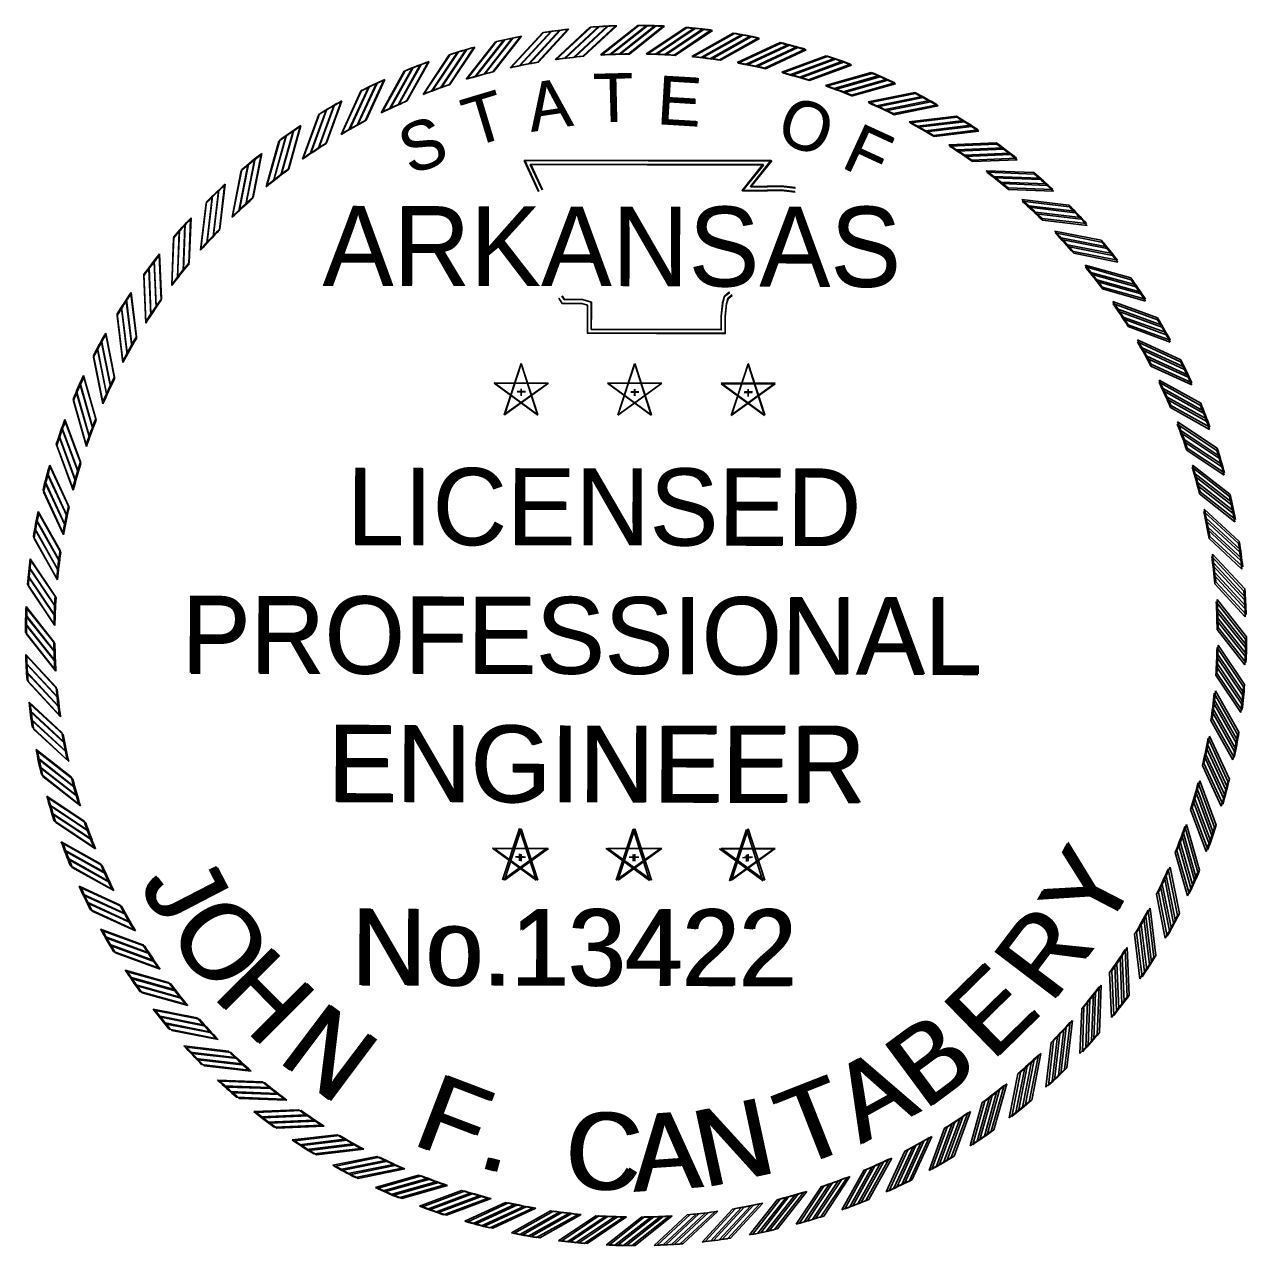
# Model space of a CAD drawing. Extents: x 1373862 to 1376999, y 1168398 to 1170455.
# Drawn here: x 1376755.4 to 1376998.5, y 1168428.9 to 1168671.8 of the extents above; entities that cross this region are included whole.
import ezdxf

# ---------------------------------------------------------------- set-up
doc = ezdxf.new("R2010")
doc.units = 0
doc.layers.add('Default', color=7, linetype='Continuous')

# ---------------------------------------------------------------- blocks, each defined once
blk = doc.blocks.new('STAR')
at = {"layer": 'Default'}
for p, q in [((-0.0001, 0.0615), (-0.0366, -0.0504)), ((0.0362, -0.0503), (0, 0.0617)), ((0.0587, 0.0188), (-0.059, 0.0189)), ((-0.0589, 0.0188), (0.0363, -0.0505)), ((-0.0365, -0.0503), (0.0589, 0.0188)), ((-0.0085, 0), (0.009, 0)), ((0, 0.0063), (0, -0.0085))]:
    blk.add_line(p, q, dxfattribs=at)
blk = doc.blocks.new('RP')
at = {"layer": 'Default'}
for p, q in [((-0.0781, 1.2656), (0.003, 1.33)), ((-0.058, 1.2667), (0.0216, 1.3299)), ((-0.0375, 1.2674), (0.0405, 1.3294)), ((-0.0176, 1.2679), (0.059, 1.3287))]:
    blk.add_line(p, q, dxfattribs=at)
for radius, start, end in [(1.33, 87.4562, 89.8699), (1.268, 90.7933, 93.5307)]:
    blk.add_arc((0, 0), radius, start, end, dxfattribs=at)

msp = doc.modelspace()

# ---------------------------------------------------------------- linework, layer by layer
at = {"layer": 'Default'}
for points in [[(1376857.59, 1168638.63), (1376854.76, 1168644.77), (1376903.8, 1168644.8), (1376899.7, 1168639.65), (1376903.03, 1168639.69), (1376905.82, 1168639.73), (1376908.6, 1168639.43)], [(1376857.69, 1168638.66), (1376854.88, 1168644.81), (1376903.92, 1168644.67), (1376899.8, 1168639.54), (1376903.13, 1168639.57), (1376905.92, 1168639.6), (1376908.7, 1168639.28)], [(1376858.3, 1168638.96), (1376855.97, 1168643.99), (1376902.19, 1168644.02), (1376898.07, 1168638.85), (1376903.04, 1168638.92), (1376905.78, 1168638.95), (1376908.51, 1168638.65)], [(1376858.39, 1168638.99), (1376856.09, 1168644.03), (1376902.3, 1168643.9), (1376898.17, 1168638.75), (1376903.14, 1168638.79), (1376905.88, 1168638.82), (1376908.61, 1168638.51)], [(1376896.07, 1168618.08), (1376895.23, 1168617.4), (1376894.96, 1168616.38), (1376894.68, 1168613.84), (1376894.68, 1168610.45), (1376867.3, 1168610.45), (1376867.3, 1168615.03), (1376867.3, 1168616.04), (1376866.19, 1168616.38), (1376862.3, 1168616.38), (1376861.61, 1168617.44)], [(1376896.1, 1168617.98), (1376895.26, 1168617.3), (1376894.98, 1168616.29), (1376894.69, 1168613.75), (1376894.68, 1168610.36), (1376867.3, 1168610.45), (1376867.32, 1168615.03), (1376867.32, 1168616.04), (1376866.21, 1168616.38), (1376862.32, 1168616.4), (1376861.63, 1168617.46)], [(1376895.58, 1168618.68), (1376894.55, 1168617.84), (1376894.19, 1168616.53), (1376893.9, 1168613.88), (1376893.9, 1168611.23), (1376868.08, 1168611.23), (1376868.08, 1168615.03), (1376868.08, 1168616.62), (1376866.31, 1168617.16), (1376862.72, 1168617.16), (1376862.26, 1168617.86)], [(1376895.61, 1168618.58), (1376894.58, 1168617.75), (1376894.21, 1168616.43), (1376893.91, 1168613.79), (1376893.91, 1168611.13), (1376868.08, 1168611.22), (1376868.1, 1168615.02), (1376868.1, 1168616.61), (1376866.33, 1168617.16), (1376862.74, 1168617.17), (1376862.28, 1168617.88)]]:
    msp.add_lwpolyline(points, dxfattribs=at)

# ---------------------------------------------------------------- block references
for name, p, xscale, yscale, rotation in [('RP', (1376877.07, 1168550.39), 91.17655343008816, 91.1765534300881, 4.500000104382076), ('RP', (1376876.87, 1168550.35), 91.17655343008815, 91.17655343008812, 4.304199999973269), ('RP', (1376877.07, 1168550.39), 91.17655343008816, 91.1765534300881, 1.0438208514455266e-07), ('RP', (1376876.87, 1168550.35), 91.17655343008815, 91.1765534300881, -0.19580000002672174), ('RP', (1376877.07, 1168550.39), 91.17655343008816, 91.17655343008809, -4.499999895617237), ('RP', (1376876.87, 1168550.35), 91.17655343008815, 91.17655343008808, -4.695800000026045), ('RP', (1376877.07, 1168550.39), 91.17655343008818, 91.17655343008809, -8.999999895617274), ('RP', (1376876.87, 1168550.35), 91.17655343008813, 91.17655343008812, -9.19580000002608), ('RP', (1376877.07, 1168550.39), 91.17655343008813, 91.17655343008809, 13.500000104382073), ('RP', (1376876.87, 1168550.35), 91.17655343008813, 91.17655343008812, 13.304199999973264), ('RP', (1376877.07, 1168550.39), 91.17655343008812, 91.17655343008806, 9.000000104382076), ('RP', (1376876.87, 1168550.35), 91.17655343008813, 91.17655343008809, 8.804199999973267), ('RP', (1376877.07, 1168550.39), 91.17655343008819, 91.17655343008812, -13.499999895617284), ('RP', (1376876.87, 1168550.35), 91.17655343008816, 91.17655343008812, -13.695800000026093), ('RP', (1376877.07, 1168550.39), 91.17655343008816, 91.1765534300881, 18.00000010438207), ('RP', (1376876.87, 1168550.35), 91.17655343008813, 91.17655343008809, 17.80419999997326), ('RP', (1376877.07, 1168550.39), 91.17655343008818, 91.1765534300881, -17.99999989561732), ('RP', (1376876.87, 1168550.35), 91.17655343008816, 91.1765534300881, -18.195800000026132), ('RP', (1376877.07, 1168550.39), 91.17655343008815, 91.1765534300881, 22.50000010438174), ('RP', (1376876.87, 1168550.35), 91.17655343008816, 91.17655343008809, 22.304199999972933), ('RP', (1376877.07, 1168550.39), 91.17655343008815, 91.17655343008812, -22.499999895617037), ('RP', (1376876.87, 1168550.35), 91.17655343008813, 91.17655343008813, -22.695800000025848), ('RP', (1376877.07, 1168550.39), 91.17655343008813, 91.17655343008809, -26.999999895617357), ('RP', (1376876.87, 1168550.35), 91.17655343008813, 91.17655343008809, -27.19580000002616), ('RP', (1376877.07, 1168550.39), 91.17655343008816, 91.17655343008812, 27.00000010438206), ('RP', (1376876.87, 1168550.35), 91.17655343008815, 91.17655343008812, 26.80419999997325), ('RP', (1376876.87, 1168550.35), 91.17655343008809, 91.17655343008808, 31.30419999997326), ('RP', (1376877.07, 1168550.39), 91.17655343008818, 91.17655343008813, -31.49999989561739), ('RP', (1376876.87, 1168550.35), 91.17655343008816, 91.17655343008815, -31.695800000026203), ('RP', (1376877.07, 1168550.39), 91.1765534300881, 91.17655343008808, 31.500000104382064), ('RP', (1376876.87, 1168550.35), 91.1765534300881, 91.1765534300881, 35.804199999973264), ('RP', (1376877.07, 1168550.39), 91.17655343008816, 91.17655343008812, -35.99999989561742), ('RP', (1376876.87, 1168550.35), 91.17655343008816, 91.17655343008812, -36.195800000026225), ('RP', (1376877.07, 1168550.39), 91.17655343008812, 91.1765534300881, 36.00000010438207), ('RP', (1376877.07, 1168550.39), 91.17655343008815, 91.17655343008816, -40.499999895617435), ('RP', (1376876.87, 1168550.35), 91.17655343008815, 91.17655343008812, -40.69580000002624), ('RP', (1376877.07, 1168550.39), 91.17655343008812, 91.1765534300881, 40.50000010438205), ('RP', (1376876.87, 1168550.35), 91.17655343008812, 91.1765534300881, 40.30419999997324), ('RP', (1376877.07, 1168550.39), 91.17655343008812, 91.17655343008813, 45.00000010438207), ('RP', (1376876.87, 1168550.35), 91.17655343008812, 91.1765534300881, 44.80419999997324), ('RP', (1376877.07, 1168550.39), 91.17655343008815, 91.1765534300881, -44.99999989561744), ('RP', (1376876.87, 1168550.35), 91.17655343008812, 91.1765534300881, -45.19580000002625), ('RP', (1376877.07, 1168550.39), 91.17655343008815, 91.17655343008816, 49.500000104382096), ('RP', (1376876.87, 1168550.35), 91.17655343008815, 91.17655343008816, 49.30419999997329), ('RP', (1376877.07, 1168550.39), 91.1765534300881, 91.1765534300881, -49.499999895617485), ('RP', (1376876.87, 1168550.35), 91.1765534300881, 91.17655343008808, -49.695800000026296), ('RP', (1376877.07, 1168550.39), 91.17655343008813, 91.17655343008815, 54.00000010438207), ('RP', (1376876.87, 1168550.35), 91.17655343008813, 91.17655343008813, 53.804199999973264), ('RP', (1376877.07, 1168550.39), 91.17655343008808, 91.17655343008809, -53.999999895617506), ('RP', (1376876.87, 1168550.35), 91.17655343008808, 91.17655343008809, -54.1958000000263), ('RP', (1376876.87, 1168550.35), 91.1765534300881, 91.17655343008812, 58.304199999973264), ('RP', (1376877.07, 1168550.39), 91.1765534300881, 91.17655343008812, 58.50000010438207), ('RP', (1376877.07, 1168550.39), 91.1765534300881, 91.17655343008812, -58.49999989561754), ('RP', (1376876.87, 1168550.35), 91.17655343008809, 91.17655343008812, -58.69580000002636), ('RP', (1376876.87, 1168550.35), 91.17655343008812, 91.17655343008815, 62.804199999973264), ('RP', (1376877.07, 1168550.39), 91.17655343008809, 91.17655343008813, -62.999999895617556), ('RP', (1376876.87, 1168550.35), 91.17655343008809, 91.17655343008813, -63.19580000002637), ('RP', (1376877.07, 1168550.39), 91.17655343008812, 91.17655343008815, 63.000000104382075), ('STAR', (1376854.14, 1168598.85), 91.17655343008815, 91.1765534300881, -0.19580000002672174), ('STAR', (1376854.18, 1168598.8), 91.17655343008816, 91.1765534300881, 1.0438208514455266e-07), ('STAR', (1376876.69, 1168598.77), 91.17655343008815, 91.1765534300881, -0.19580000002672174), ('STAR', (1376876.73, 1168598.8), 91.17655343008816, 91.1765534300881, 1.0438208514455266e-07), ('STAR', (1376899.25, 1168598.69), 91.17655343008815, 91.1765534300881, -0.19580000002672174), ('STAR', (1376899.29, 1168598.8), 91.17655343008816, 91.1765534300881, 1.0438208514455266e-07), ('RP', (1376877.07, 1168550.39), 91.1765534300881, 91.17655343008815, -67.49999989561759), ('RP', (1376876.87, 1168550.35), 91.1765534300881, 91.17655343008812, 67.30419999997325), ('RP', (1376877.07, 1168550.39), 91.1765534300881, 91.17655343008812, 67.50000010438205), ('RP', (1376876.87, 1168550.35), 91.1765534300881, 91.17655343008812, -67.69580000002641), ('RP', (1376876.87, 1168550.35), 91.1765534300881, 91.17655343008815, -72.19580000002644), ('RP', (1376877.07, 1168550.39), 91.1765534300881, 91.17655343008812, -71.99999989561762), ('RP', (1376876.87, 1168550.35), 91.17655343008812, 91.17655343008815, 71.80419999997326), ('RP', (1376877.07, 1168550.39), 91.1765534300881, 91.17655343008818, 72.00000010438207), ('RP', (1376876.87, 1168550.35), 91.17655343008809, 91.17655343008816, 76.30419999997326), ('RP', (1376877.07, 1168550.39), 91.17655343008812, 91.17655343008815, 76.50000010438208), ('RP', (1376876.87, 1168550.35), 91.17655343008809, 91.17655343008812, -76.69580000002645), ('RP', (1376877.07, 1168550.39), 91.17655343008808, 91.1765534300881, -76.49999989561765), ('RP', (1376877.07, 1168550.39), 91.17655343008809, 91.17655343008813, -80.99999989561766), ('RP', (1376876.87, 1168550.35), 91.17655343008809, 91.17655343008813, 80.80419999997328), ('RP', (1376877.07, 1168550.39), 91.1765534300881, 91.17655343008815, 81.0000001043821), ('RP', (1376876.87, 1168550.35), 91.1765534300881, 91.17655343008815, -81.19580000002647), ('RP', (1376877.07, 1168550.39), 91.17655343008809, 91.17655343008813, -85.49999989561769), ('RP', (1376876.87, 1168550.35), 91.17655343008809, 91.17655343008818, 85.30419999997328), ('RP', (1376877.07, 1168550.39), 91.17655343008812, 91.17655343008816, 85.50000010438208), ('RP', (1376876.87, 1168550.35), 91.17655343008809, 91.17655343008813, -85.69580000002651), ('RP', (1376876.87, 1168550.35), 91.17655343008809, 91.17655343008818, -90.19580000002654), ('RP', (1376877.07, 1168550.39), 91.1765534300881, 91.17655343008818, -89.99999989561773), ('RP', (1376876.87, 1168550.35), 91.1765534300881, 91.17655343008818, 89.80419999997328), ('RP', (1376877.07, 1168550.39), 91.17655343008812, 91.17655343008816, 90.0000001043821), ('RP', (1376876.87, 1168550.35), 91.17655343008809, 91.17655343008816, -94.69580000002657), ('RP', (1376877.07, 1168550.39), 91.17655343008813, 91.17655343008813, -94.49999989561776), ('RP', (1376876.87, 1168550.35), 91.17655343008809, 91.17655343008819, 94.30419999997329), ('RP', (1376877.07, 1168550.39), 91.1765534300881, 91.1765534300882, 94.5000001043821), ('RP', (1376876.87, 1168550.35), 91.1765534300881, 91.17655343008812, 98.8041999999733), ('RP', (1376877.07, 1168550.39), 91.17655343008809, 91.17655343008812, 99.0000001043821), ('RP', (1376876.87, 1168550.35), 91.1765534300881, 91.17655343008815, -99.19580000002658), ('RP', (1376877.07, 1168550.39), 91.1765534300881, 91.17655343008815, -98.99999989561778), ('RP', (1376877.07, 1168550.39), 91.1765534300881, 91.17655343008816, -103.49999989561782), ('RP', (1376876.87, 1168550.35), 91.1765534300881, 91.17655343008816, 103.30419999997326), ('RP', (1376877.07, 1168550.39), 91.1765534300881, 91.17655343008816, 103.50000010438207), ('RP', (1376876.87, 1168550.35), 91.1765534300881, 91.17655343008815, -103.69580000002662), ('RP', (1376876.87, 1168550.35), 91.1765534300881, 91.17655343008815, -108.19580000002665), ('RP', (1376877.07, 1168550.39), 91.17655343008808, 91.17655343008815, -107.99999989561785), ('RP', (1376876.87, 1168550.35), 91.17655343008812, 91.17655343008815, 107.80419999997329), ('RP', (1376877.07, 1168550.39), 91.17655343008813, 91.17655343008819, 108.0000001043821), ('RP', (1376876.87, 1168550.35), 91.1765534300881, 91.17655343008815, 112.30419999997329), ('RP', (1376877.07, 1168550.39), 91.1765534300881, 91.17655343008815, 112.5000001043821), ('STAR', (1376853.82, 1168506.37), 91.17655343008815, 91.1765534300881, -0.19580000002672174), ('STAR', (1376854.18, 1168506.32), 91.17655343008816, 91.1765534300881, 1.0438208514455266e-07), ('STAR', (1376876.38, 1168506.29), 91.17655343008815, 91.1765534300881, -0.19580000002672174), ('STAR', (1376876.73, 1168506.32), 91.17655343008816, 91.1765534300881, 1.0438208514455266e-07), ('STAR', (1376898.93, 1168506.21), 91.17655343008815, 91.1765534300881, -0.19580000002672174), ('STAR', (1376899.29, 1168506.32), 91.17655343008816, 91.1765534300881, 1.0438208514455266e-07), ('RP', (1376876.87, 1168550.35), 91.1765534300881, 91.17655343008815, -112.69580000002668), ('RP', (1376877.07, 1168550.39), 91.17655343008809, 91.17655343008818, -112.49999989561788), ('RP', (1376876.87, 1168550.35), 91.17655343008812, 91.17655343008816, -117.19580000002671), ('RP', (1376877.07, 1168550.39), 91.17655343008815, 91.17655343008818, -116.9999998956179), ('RP', (1376876.87, 1168550.35), 91.17655343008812, 91.17655343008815, 116.80419999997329), ('RP', (1376877.07, 1168550.39), 91.17655343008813, 91.17655343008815, 117.0000001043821), ('RP', (1376877.07, 1168550.39), 91.17655343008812, 91.17655343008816, -121.4999998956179), ('RP', (1376876.87, 1168550.35), 91.17655343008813, 91.17655343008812, 121.30419999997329), ('RP', (1376877.07, 1168550.39), 91.17655343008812, 91.17655343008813, 121.5000001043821), ('RP', (1376876.87, 1168550.35), 91.17655343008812, 91.17655343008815, -121.69580000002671), ('RP', (1376876.87, 1168550.35), 91.17655343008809, 91.17655343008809, 125.80419999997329), ('RP', (1376877.07, 1168550.39), 91.17655343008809, 91.17655343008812, 126.00000010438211), ('RP', (1376876.87, 1168550.35), 91.17655343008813, 91.17655343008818, -126.19580000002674), ('RP', (1376877.07, 1168550.39), 91.17655343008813, 91.17655343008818, -125.99999989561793), ('RP', (1376876.87, 1168550.35), 91.1765534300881, 91.17655343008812, 130.3041999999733), ('RP', (1376877.07, 1168550.39), 91.17655343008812, 91.1765534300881, 130.50000010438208), ('RP', (1376876.87, 1168550.35), 91.1765534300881, 91.17655343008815, -130.6958000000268), ('RP', (1376877.07, 1168550.39), 91.17655343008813, 91.17655343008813, -130.49999989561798), ('RP', (1376876.87, 1168550.35), 91.17655343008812, 91.1765534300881, 134.80419999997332), ('RP', (1376877.07, 1168550.39), 91.17655343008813, 91.17655343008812, 135.00000010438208), ('RP', (1376876.87, 1168550.35), 91.17655343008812, 91.1765534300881, -135.19580000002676), ('RP', (1376877.07, 1168550.39), 91.17655343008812, 91.17655343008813, -134.99999989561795), ('RP', (1376877.07, 1168550.39), 91.17655343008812, 91.17655343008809, -139.49999989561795), ('RP', (1376876.87, 1168550.35), 91.17655343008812, 91.17655343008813, 139.30419999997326), ('RP', (1376877.07, 1168550.39), 91.17655343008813, 91.17655343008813, 139.50000010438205), ('RP', (1376876.87, 1168550.35), 91.1765534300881, 91.17655343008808, -139.69580000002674), ('RP', (1376876.87, 1168550.35), 91.17655343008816, 91.17655343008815, 143.8041999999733), ('RP', (1376877.07, 1168550.39), 91.17655343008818, 91.17655343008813, 144.00000010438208), ('RP', (1376876.87, 1168550.35), 91.17655343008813, 91.17655343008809, -144.19580000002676), ('RP', (1376877.07, 1168550.39), 91.17655343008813, 91.17655343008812, -143.99999989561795), ('RP', (1376876.87, 1168550.35), 91.17655343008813, 91.17655343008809, 148.3041999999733), ('RP', (1376876.87, 1168550.35), 91.1765534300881, 91.17655343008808, -148.69580000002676), ('RP', (1376877.07, 1168550.39), 91.1765534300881, 91.1765534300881, -148.49999989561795), ('RP', (1376877.07, 1168550.39), 91.17655343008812, 91.1765534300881, 148.50000010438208), ('RP', (1376876.87, 1168550.35), 91.17655343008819, 91.17655343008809, 152.8041999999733), ('RP', (1376877.07, 1168550.39), 91.17655343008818, 91.17655343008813, 153.00000010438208), ('RP', (1376876.87, 1168550.35), 91.17655343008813, 91.17655343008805, -153.1958000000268), ('RP', (1376877.07, 1168550.39), 91.17655343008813, 91.17655343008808, -152.99999989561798), ('RP', (1376876.87, 1168550.35), 91.17655343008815, 91.17655343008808, 157.3041999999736), ('RP', (1376877.07, 1168550.39), 91.17655343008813, 91.17655343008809, 157.50000010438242), ('RP', (1376876.87, 1168550.35), 91.17655343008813, 91.17655343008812, -157.6958000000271), ('RP', (1376877.07, 1168550.39), 91.17655343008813, 91.17655343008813, -157.4999998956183), ('RP', (1376877.07, 1168550.39), 91.17655343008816, 91.1765534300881, -161.99999989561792), ('RP', (1376876.87, 1168550.35), 91.17655343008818, 91.17655343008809, 161.8041999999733), ('RP', (1376877.07, 1168550.39), 91.17655343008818, 91.1765534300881, 162.00000010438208), ('RP', (1376876.87, 1168550.35), 91.17655343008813, 91.17655343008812, -162.19580000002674), ('RP', (1376876.87, 1168550.35), 91.17655343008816, 91.17655343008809, 166.3041999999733), ('RP', (1376877.07, 1168550.39), 91.17655343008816, 91.17655343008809, 166.50000010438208), ('RP', (1376876.87, 1168550.35), 91.17655343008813, 91.17655343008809, -166.69580000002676), ('RP', (1376877.07, 1168550.39), 91.17655343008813, 91.17655343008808, -166.49999989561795), ('RP', (1376876.87, 1168550.35), 91.17655343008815, 91.1765534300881, 170.8041999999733), ('RP', (1376877.07, 1168550.39), 91.17655343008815, 91.1765534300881, 171.00000010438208), ('RP', (1376876.87, 1168550.35), 91.17655343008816, 91.1765534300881, 175.3041999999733), ('RP', (1376877.07, 1168550.39), 91.17655343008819, 91.17655343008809, 175.50000010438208), ('RP', (1376876.87, 1168550.35), 91.17655343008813, 91.17655343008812, -175.69580000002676), ('RP', (1376877.07, 1168550.39), 91.17655343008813, 91.17655343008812, -175.49999989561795), ('RP', (1376876.87, 1168550.35), 91.1765534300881, 91.1765534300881, -171.19580000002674), ('RP', (1376877.07, 1168550.39), 91.17655343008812, 91.17655343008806, -170.99999989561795), ('RP', (1376876.87, 1168550.35), 91.17655343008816, 91.17655343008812, 179.8041999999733), ('RP', (1376877.07, 1168550.39), 91.17655343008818, 91.1765534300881, -179.99999989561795)]:
    msp.add_blockref(name, p, dxfattribs=dict(at, xscale=xscale, yscale=yscale, rotation=rotation))

# ---------------------------------------------------------------- texts
for s, height, rotation, p in [('T', 9.67, 1.4789, (1376868.59, 1168652.36)), ('T', 9.67, 1.2831, (1376868.73, 1168652.36)), ('E', 9.67, 356.672, (1376880.97, 1168652.07)), ('E', 9.67, 356.4762, (1376881.11, 1168652.02)), ('A', 9.67, 8.6788, (1376856.1, 1168650.44)), ('A', 9.67, 8.483, (1376856.23, 1168650.47)), ('T', 9.67, 16.9015, (1376844.35, 1168647.37)), ('T', 9.67, 16.7057, (1376844.48, 1168647.45)), ('O', 9.67, 341.2218, (1376904.46, 1168648.75)), ('O', 9.67, 341.026, (1376904.59, 1168648.62)), ('S', 9.67, 19.7726, (1376832.05, 1168641.85)), ('S', 9.67, 19.5768, (1376832.16, 1168641.97)), ('F', 9.67, 335.3628, (1376917.5, 1168643.65)), ('F', 9.67, 335.167, (1376917.61, 1168643.48)), ('ARKANSAS', 15.788, 0, (1376814.67, 1168619.84)), ('ARKANSAS', 15.788, 359.8042, (1376814.7, 1168620.02)), ('LICENSED', 15.285, 359.8042, (1376819.43, 1168568.47)), ('LICENSED', 15.285, 0, (1376819.57, 1168568.31)), ('PROFESSIONAL', 15.2848, 359.8042, (1376786.59, 1168543.02)), ('PROFESSIONAL', 15.2848, 0, (1376786.82, 1168542.74)), ('ENGINEER', 15.285, 359.8042, (1376815.61, 1168517.36)), ('ENGINEER', 15.285, 0, (1376815.93, 1168517.18)), ('Y', 15.28, 62.5392, (1376970.04, 1168490.37)), ('Y', 15.28, 62.735, (1376970.45, 1168490.72)), ('J', 15.28, 297.2813, (1376778.07, 1168501.23)), ('J', 15.28, 297.4771, (1376778.44, 1168500.92)), ('O', 15.28, 304.1899, (1376783.48, 1168491.85)), ('O', 15.28, 304.3857, (1376783.89, 1168491.57)), ('No.13422', 15.225, 359.8042, (1376820.31, 1168480.91)), ('No.13422', 15.225, 0, (1376820.76, 1168480.75)), ('R', 15.28, 52.7437, (1376959.37, 1168476.91)), ('R', 15.28, 52.9395, (1376959.83, 1168477.22)), ('H', 15.28, 314.7447, (1376792.5, 1168478.68)), ('H', 15.28, 314.9405, (1376792.95, 1168478.43)), ('E', 15.28, 44.306, (1376947.73, 1168465.53)), ('E', 15.28, 44.5018, (1376948.22, 1168465.81)), ('N', 15.28, 322.9417, (1376805.4, 1168465.91)), ('N', 15.28, 323.1375, (1376805.9, 1168465.69)), ('B', 15.28, 36.505, (1376934.24, 1168455.8)), ('B', 15.28, 36.7008, (1376934.77, 1168456.03)), ('A', 15.28, 28.8562, (1376921.54, 1168449.13)), ('A', 15.28, 29.052, (1376922.09, 1168449.32)), ('F', 15.28, 339.0288, (1376832.08, 1168449.35)), ('F', 15.28, 339.2246, (1376832.63, 1168449.23)), ('T', 15.28, 21.4329, (1376908.84, 1168444.35)), ('T', 15.28, 21.6287, (1376909.4, 1168444.5)), ('N', 15.28, 12.0703, (1376890.4, 1168440.54)), ('N', 15.28, 12.2661, (1376890.98, 1168440.62)), ('C', 15.28, 356.1028, (1376862.41, 1168440.77)), ('C', 15.28, 356.2986, (1376862.99, 1168440.76)), ('A', 15.28, 3.9092, (1376876.43, 1168439.76)), ('A', 15.28, 4.105, (1376877.01, 1168439.79)), ('.', 15.28, 344.7037, (1376845.12, 1168444.83)), ('.', 15.28, 344.8995, (1376845.69, 1168444.76))]:
    msp.add_text(s, height=height, rotation=rotation, dxfattribs=at).set_placement(p)

doc.saveas('drawing.dxf')
